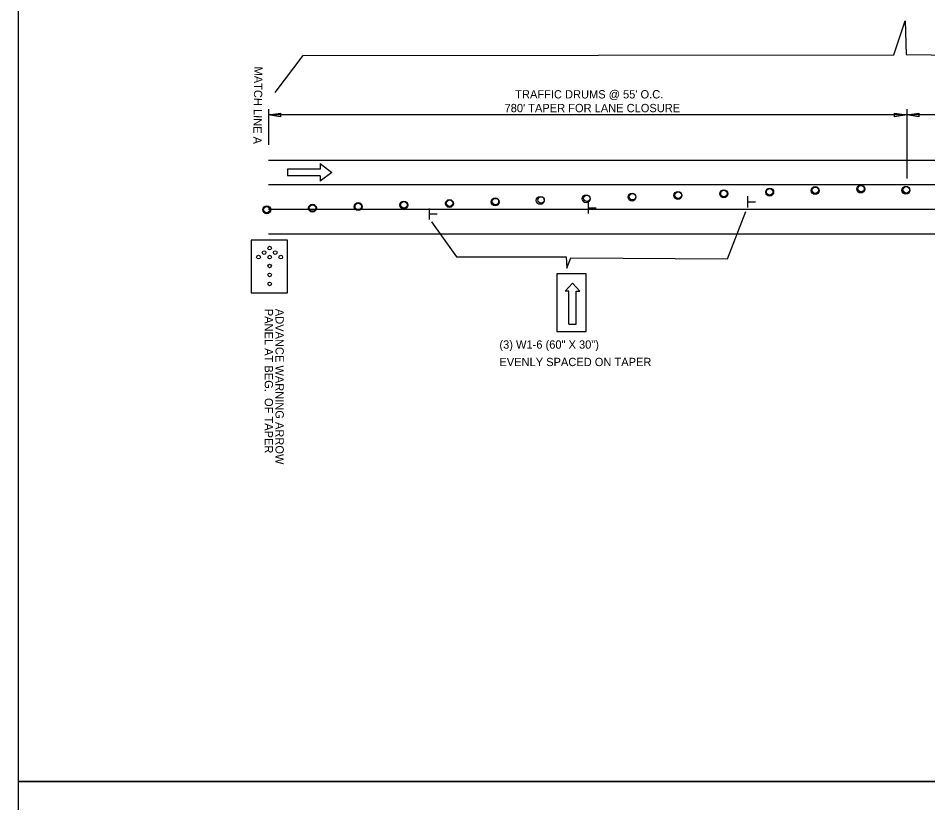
# Model space of a CAD drawing. Extents: x -100 to 745, y -1581 to -107.
# Drawn here: x 574.8 to 639.2, y -598.3 to -542.7 of the extents above; entities that cross this region are included whole.
import ezdxf

# ---------------------------------------------------------------- set-up
doc = ezdxf.new("R2010")
doc.units = 0
doc.layers.add('Default', color=7, linetype='Continuous')
doc.layers.add('R_Proposed Road', color=7, linetype='Continuous')

msp = doc.modelspace()

# ---------------------------------------------------------------- linework, layer by layer
at = {"layer": 'Default'}
for p, q in [((592.482, -549.174), (592.482, -551.701)), ((637.683, -549.174), (637.683, -551.924)), ((592.482, -549.588), (593.351, -549.458)), ((637.683, -549.588), (592.482, -549.588)), ((593.351, -549.719), (592.482, -549.588)), ((593.351, -549.458), (593.351, -549.719)), ((636.814, -549.719), (636.814, -549.458)), ((636.814, -549.458), (637.683, -549.588)), ((637.683, -549.588), (636.814, -549.719)), ((637.683, -549.441), (637.683, -554.076)), ((637.683, -549.588), (638.552, -549.458)), ((663.76, -549.588), (637.683, -549.588)), ((638.552, -549.719), (637.683, -549.588)), ((637.683, -549.823), (637.683, -553.48)), ((638.552, -549.458), (638.552, -549.719)), ((592.482, -552.786), (619.838, -552.786)), ((596.161, -553.023), (596.161, -553.418)), ((596.161, -553.023), (596.982, -553.655)), ((619.838, -552.786), (678.107, -552.786)), ((596.161, -553.418), (593.836, -553.418)), ((593.836, -553.418), (593.836, -553.892)), ((596.161, -553.892), (593.836, -553.892)), ((596.982, -553.655), (596.161, -554.287)), ((596.161, -553.892), (596.161, -554.287)), ((592.482, -554.524), (620.055, -554.524)), ((620.055, -554.524), (678.324, -554.524)), ((615.155, -556.558), (615.155, -555.776)), ((626.426, -556.132), (626.426, -555.35)), ((626.438, -555.743), (626.972, -555.743)), ((592.482, -556.263), (620.41, -556.263)), ((603.884, -556.985), (603.884, -556.203)), ((615.167, -556.169), (615.701, -556.169)), ((620.41, -556.263), (678.678, -556.263)), ((603.896, -556.596), (604.43, -556.596)), ((592.482, -558.001), (619.891, -558.001)), ((619.891, -558.001), (678.888, -558.001)), ((613.502, -562.075), (614.021, -561.506)), ((614.021, -561.506), (614.54, -562.075)), ((613.761, -562.075), (613.502, -562.075)), ((613.761, -564.406), (613.761, -562.075)), ((614.28, -564.406), (614.28, -562.075)), ((614.28, -562.075), (614.54, -562.075)), ((613.761, -564.406), (614.28, -564.406))]:
    msp.add_line(p, q, dxfattribs=at)
for points in [[(592.968, -548.002), (594.944, -545.384), (636.77, -545.336), (637.575, -542.917), (637.648, -545.301), (662.316, -545.634), (663.458, -548.232)], [(604.029, -557.149), (605.795, -559.63), (613.56, -559.63), (613.628, -560.448), (613.901, -559.698), (625.004, -559.766), (626.297, -556.419)]]:
    msp.add_lwpolyline(points, dxfattribs=at)
for points in [[(591.256, -558.461), (591.256, -562.185), (593.833, -562.185), (593.833, -558.461)], [(612.907, -560.84), (612.907, -564.927), (614.997, -564.927), (614.997, -560.84)]]:
    msp.add_lwpolyline(points, close=True, dxfattribs=at)
for centre, radius in [((634.429, -554.832), 0.281), ((618.233, -555.402), 0.281), ((618.269, -555.378), 0.229), ((621.483, -555.286), 0.281), ((621.506, -555.263), 0.229), ((624.733, -555.169), 0.281), ((624.742, -555.148), 0.229), ((627.983, -555.053), 0.281), ((627.979, -555.034), 0.229), ((631.204, -554.943), 0.281), ((631.216, -554.919), 0.229), ((634.453, -554.804), 0.229), ((637.627, -554.924), 0.281), ((637.65, -554.891), 0.229), ((637.662, -554.892), 0.229), ((598.843, -556.078), 0.281), ((598.848, -556.066), 0.229), ((602.077, -555.967), 0.281), ((602.085, -555.951), 0.229), ((605.31, -555.856), 0.281), ((605.322, -555.836), 0.229), ((608.544, -555.745), 0.281), ((608.559, -555.722), 0.229), ((611.733, -555.635), 0.281), ((611.795, -555.607), 0.229), ((614.983, -555.519), 0.281), ((615.032, -555.492), 0.229), ((592.376, -556.299), 0.281), ((592.362, -556.294), 0.229), ((592.375, -556.295), 0.229), ((595.61, -556.188), 0.281), ((595.611, -556.181), 0.229), ((592.574, -559.019), 0.131), ((591.784, -559.651), 0.131), ((592.179, -559.335), 0.131), ((592.574, -559.651), 0.131), ((592.968, -559.335), 0.131), ((593.363, -559.651), 0.131), ((592.574, -560.283), 0.131), ((592.574, -560.916), 0.131), ((592.574, -561.548), 0.131)]:
    msp.add_circle(centre, radius, dxfattribs=at)
at = {"layer": 'R_Proposed Road'}
for points in [[(574.769, -486.786), (574.769, -596.786), (744.769, -596.786), (744.769, -486.786)], [(574.769, -596.786), (574.769, -706.786), (744.769, -706.786), (744.769, -596.786)]]:
    msp.add_lwpolyline(points, close=True, dxfattribs=at)

# ---------------------------------------------------------------- texts
at = {"layer": 'Default'}
for s, rotation, p in [('MATCH LINE A', 269.19408, (591.489, -546.156)), ('PANEL AT BEG.  OF TAPER', 270, (592.224, -563.315)), ('ADVANCE WARNING ARROW', 270, (592.988, -563.315)), ('(3) W1-6 (60" X 30")', 0.00754, (608.845, -566.137)), ('EVENLY SPACED ON TAPER', 0.00754, (608.845, -567.372))]:
    msp.add_text(s, height=0.5862, rotation=rotation, dxfattribs=at).set_placement(p)
for s, p in [("TRAFFIC DRUMS @ 55' O.C.", (609.965, -548.419)), ("780' TAPER FOR LANE CLOSURE", (609.209, -549.392))]:
    msp.add_text(s, height=0.5862, dxfattribs=at).set_placement(p)

doc.saveas('drawing.dxf')
